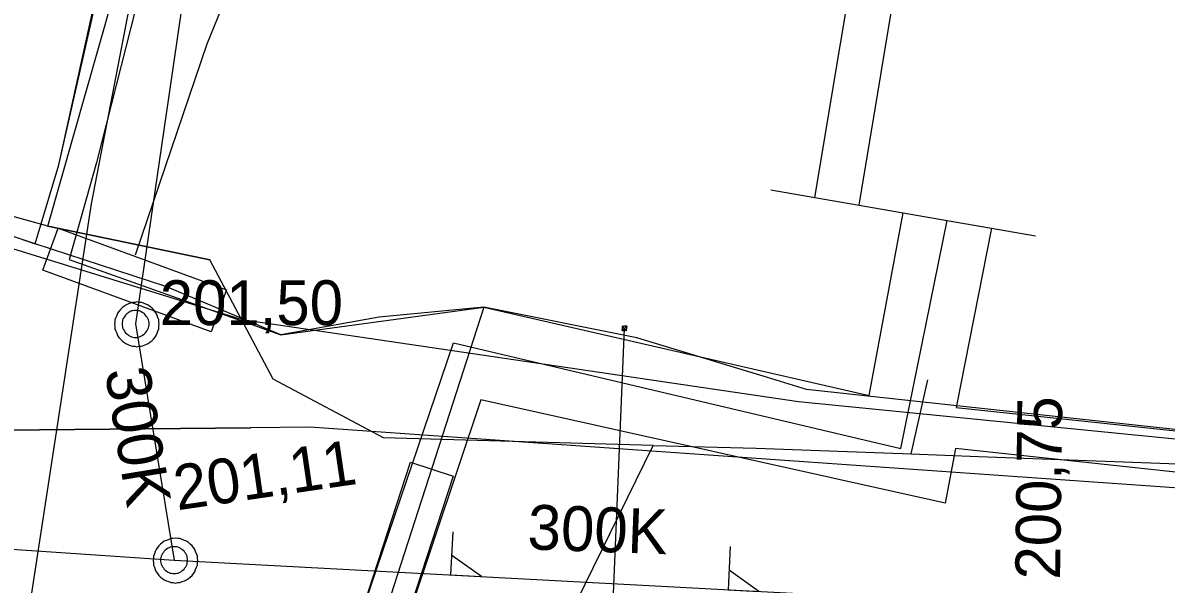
# Model space of a CAD drawing. Extents: x -746464 to -745690, y -1051581 to -1049993.
# Drawn here: x -746411.28 to -746385.76, y -1051025.44 to -1051012.91 of the extents above; entities that cross this region are included whole.
import ezdxf

# ---------------------------------------------------------------- set-up
doc = ezdxf.new("R2010")
doc.units = 0
for name, color, linetype in [('04_CETIN_NN', 7, 'Continuous'), ('04_CETIN_sdelovaci_podzem', 7, 'Continuous'), ('45_Eltodo_sdelovaci_kabel_ovladaci', 7, 'Continuous'), ('48_Prazs_plynarenska_STL', 7, 'Continuous'), ('51_PVaK_kanal_jednotna_overena poloha_rad', 7, 'Continuous'), ('51_PVaK_kanal_objekty', 7, 'Continuous'), ('51_PVaK_kanal_popisy', 7, 'Continuous'), ('51_PVaK_vodovod_chranicky_objekty', 7, 'Continuous'), ('51_PVaK_vodovod_overena poloha_pripojka', 7, 'Continuous'), ('55_PREdi_chranicky', 7, 'Continuous'), ('55_PREdi_NN', 7, 'Continuous'), ('55_PREdi_stavby_popisy', 7, 'Continuous')]:
    doc.layers.add(name, color=color, linetype=linetype)

msp = doc.modelspace()

# ---------------------------------------------------------------- linework, layer by layer
at = {"layer": '04_CETIN_NN'}
for points in [[(-746401.2, -1051030.47), (-746397.21, -1051022.34)], [(-746397.21, -1051022.34), (-746394.91, -1051022.4), (-746391.45, -1051022.53)], [(-746391.45, -1051022.53), (-746389.95, -1051022.59)], [(-746389.95, -1051022.59), (-746379.23, -1051022.98), (-746377.8, -1051022.62), (-746376.35, -1051023.07), (-746368.44, -1051023.67)]]:
    msp.add_lwpolyline(points, dxfattribs=at)
at = {"layer": '04_CETIN_sdelovaci_podzem'}
for points in [[(-746410.72, -1051017.45), (-746409.28, -1051012.4), (-746408.32, -1051005.09)], [(-746410.72, -1051017.45), (-746422.5, -1051014.18), (-746428.14, -1051011.55)], [(-746410.72, -1051017.45), (-746407.1, -1051018.2)], [(-746397.21, -1051022.34), (-746403.23, -1051022.17), (-746405.69, -1051020.86), (-746407.1, -1051018.2), (-746410.72, -1051017.45)], [(-746391.45, -1051022.53), (-746391.08, -1051020.88)], [(-746384.52, -1051023.36), (-746404.87, -1051021.93), (-746406.19, -1051021.95), (-746411.69, -1051022), (-746412.67, -1051021.99), (-746422.41, -1051022.74), (-746428.03, -1051023.83), (-746434.88, -1051025.34)], [(-746411.69, -1051022), (-746406.19, -1051021.95)], [(-746401.2, -1051030.47), (-746397.21, -1051022.34)], [(-746401.2, -1051030.47), (-746397.21, -1051022.34)], [(-746397.21, -1051022.34), (-746394.91, -1051022.4), (-746391.45, -1051022.53)], [(-746391.45, -1051022.53), (-746389.95, -1051022.59)], [(-746389.95, -1051022.59), (-746379.23, -1051022.98), (-746377.8, -1051022.62), (-746376.35, -1051023.07), (-746368.44, -1051023.67)]]:
    msp.add_lwpolyline(points, dxfattribs=at)
at = {"layer": '45_Eltodo_sdelovaci_kabel_ovladaci'}
msp.add_lwpolyline([(-746458.107, -1051040.596), (-746452.238, -1051038.914), (-746452.533, -1051024.817), (-746441.647, -1051021.908), (-746427.884, -1051017.81), (-746425.007, -1051017.632), (-746423.494, -1051014.247), (-746406.379, -1051019.532), (-746393.969, -1051021.364), (-746377.076, -1051023.037), (-746371.357, -1051023.39), (-746350.592, -1051020.748), (-746343.378, -1051018.106), (-746337.043, -1051014.584), (-746330.796, -1051018.194), (-746332.907, -1051022.157), (-746327.98, -1051025.591), (-746302.693, -1051026.653), (-746280.345, -1051027.533), (-746279.938, -1051027.788)], dxfattribs=at)
at = {"layer": '48_Prazs_plynarenska_STL'}
msp.add_lwpolyline([(-746411.209, -1051026.506), (-746409.74, -1051016.95), (-746407.07, -1051003.13), (-746406.45, -1050996.4), (-746406.4, -1050995.95)], dxfattribs=at)
at = {"layer": '51_PVaK_kanal_jednotna_overena poloha_rad'}
for p, q in [((-746408.76, -1051019.63), (-746407.9, -1051024.9)), ((-746407.9, -1051024.9), (-746388.25, -1051025.95))]:
    msp.add_line(p, q, dxfattribs=at)
for points in [[(-746405.53, -1050997.46), (-746406.021, -1051000.828), (-746406.251, -1051002.412), (-746408.76, -1051019.63)], [(-746423.55, -1051023.85), (-746414.385, -1051024.465), (-746407.9, -1051024.9)]]:
    msp.add_lwpolyline(points, dxfattribs=at)
at = {"layer": '51_PVaK_kanal_objekty'}
for points in [[(-746408.23, -1051019.64), (-746408.24, -1051019.59), (-746408.24, -1051019.54), (-746408.26, -1051019.49), (-746408.28, -1051019.44), (-746408.3, -1051019.39), (-746408.33, -1051019.35), (-746408.36, -1051019.31), (-746408.4, -1051019.27), (-746408.44, -1051019.24), (-746408.48, -1051019.21), (-746408.53, -1051019.19), (-746408.58, -1051019.17), (-746408.63, -1051019.15), (-746408.68, -1051019.15), (-746408.73, -1051019.14), (-746408.78, -1051019.15), (-746408.83, -1051019.15), (-746408.88, -1051019.17), (-746408.93, -1051019.19), (-746408.98, -1051019.21), (-746409.02, -1051019.24), (-746409.06, -1051019.27), (-746409.1, -1051019.31), (-746409.13, -1051019.35), (-746409.16, -1051019.39), (-746409.18, -1051019.44), (-746409.2, -1051019.49), (-746409.22, -1051019.54), (-746409.22, -1051019.59), (-746409.23, -1051019.64), (-746409.22, -1051019.69), (-746409.22, -1051019.74), (-746409.2, -1051019.79), (-746409.18, -1051019.84), (-746409.16, -1051019.89), (-746409.13, -1051019.93), (-746409.1, -1051019.97), (-746409.06, -1051020.01), (-746409.02, -1051020.04), (-746408.98, -1051020.07), (-746408.93, -1051020.09), (-746408.88, -1051020.11), (-746408.83, -1051020.13), (-746408.78, -1051020.13), (-746408.73, -1051020.14), (-746408.68, -1051020.13), (-746408.63, -1051020.13), (-746408.58, -1051020.11), (-746408.53, -1051020.09), (-746408.48, -1051020.07), (-746408.44, -1051020.04), (-746408.4, -1051020.01), (-746408.36, -1051019.97), (-746408.33, -1051019.93), (-746408.3, -1051019.89), (-746408.28, -1051019.84), (-746408.26, -1051019.79), (-746408.24, -1051019.74), (-746408.24, -1051019.69), (-746408.23, -1051019.64)], [(-746408.46, -1051019.63), (-746408.46, -1051019.6), (-746408.466, -1051019.57), (-746408.472, -1051019.54), (-746408.484, -1051019.51), (-746408.502, -1051019.48), (-746408.52, -1051019.456), (-746408.538, -1051019.432), (-746408.562, -1051019.408), (-746408.586, -1051019.39), (-746408.61, -1051019.372), (-746408.64, -1051019.354), (-746408.67, -1051019.342), (-746408.7, -1051019.336), (-746408.73, -1051019.33), (-746408.76, -1051019.33), (-746408.79, -1051019.33), (-746408.82, -1051019.336), (-746408.85, -1051019.342), (-746408.88, -1051019.354), (-746408.91, -1051019.372), (-746408.934, -1051019.39), (-746408.958, -1051019.408), (-746408.982, -1051019.432), (-746409, -1051019.456), (-746409.018, -1051019.48), (-746409.036, -1051019.51), (-746409.048, -1051019.54), (-746409.054, -1051019.57), (-746409.06, -1051019.6), (-746409.06, -1051019.63), (-746409.06, -1051019.66), (-746409.054, -1051019.69), (-746409.048, -1051019.72), (-746409.036, -1051019.75), (-746409.018, -1051019.78), (-746409, -1051019.804), (-746408.982, -1051019.828), (-746408.958, -1051019.852), (-746408.934, -1051019.87), (-746408.91, -1051019.888), (-746408.88, -1051019.906), (-746408.85, -1051019.918), (-746408.82, -1051019.924), (-746408.79, -1051019.93), (-746408.76, -1051019.93), (-746408.73, -1051019.93), (-746408.7, -1051019.924), (-746408.67, -1051019.918), (-746408.64, -1051019.906), (-746408.61, -1051019.888), (-746408.586, -1051019.87), (-746408.562, -1051019.852), (-746408.538, -1051019.828), (-746408.52, -1051019.804), (-746408.502, -1051019.78), (-746408.484, -1051019.75), (-746408.472, -1051019.72), (-746408.466, -1051019.69), (-746408.46, -1051019.66), (-746408.46, -1051019.63)], [(-746401.678, -1051024.266), (-746401.729, -1051025.23), (-746401.042, -1051025.266), (-746401.706, -1051024.795)], [(-746407.37, -1051024.91), (-746407.38, -1051024.86), (-746407.38, -1051024.81), (-746407.4, -1051024.76), (-746407.42, -1051024.71), (-746407.44, -1051024.66), (-746407.47, -1051024.62), (-746407.5, -1051024.58), (-746407.54, -1051024.54), (-746407.58, -1051024.51), (-746407.62, -1051024.48), (-746407.67, -1051024.46), (-746407.72, -1051024.44), (-746407.77, -1051024.42), (-746407.82, -1051024.42), (-746407.87, -1051024.41), (-746407.92, -1051024.42), (-746407.97, -1051024.42), (-746408.02, -1051024.44), (-746408.07, -1051024.46), (-746408.12, -1051024.48), (-746408.16, -1051024.51), (-746408.2, -1051024.54), (-746408.24, -1051024.58), (-746408.27, -1051024.62), (-746408.3, -1051024.66), (-746408.32, -1051024.71), (-746408.34, -1051024.76), (-746408.36, -1051024.81), (-746408.36, -1051024.86), (-746408.37, -1051024.91), (-746408.36, -1051024.96), (-746408.36, -1051025.01), (-746408.34, -1051025.06), (-746408.32, -1051025.11), (-746408.3, -1051025.16), (-746408.27, -1051025.2), (-746408.24, -1051025.24), (-746408.2, -1051025.28), (-746408.16, -1051025.31), (-746408.12, -1051025.34), (-746408.07, -1051025.36), (-746408.02, -1051025.38), (-746407.97, -1051025.4), (-746407.92, -1051025.4), (-746407.87, -1051025.41), (-746407.82, -1051025.4), (-746407.77, -1051025.4), (-746407.72, -1051025.38), (-746407.67, -1051025.36), (-746407.62, -1051025.34), (-746407.58, -1051025.31), (-746407.54, -1051025.28), (-746407.5, -1051025.24), (-746407.47, -1051025.2), (-746407.44, -1051025.16), (-746407.42, -1051025.11), (-746407.4, -1051025.06), (-746407.38, -1051025.01), (-746407.38, -1051024.96), (-746407.37, -1051024.91)], [(-746407.6, -1051024.9), (-746407.6, -1051024.87), (-746407.606, -1051024.84), (-746407.612, -1051024.81), (-746407.624, -1051024.78), (-746407.642, -1051024.75), (-746407.66, -1051024.726), (-746407.678, -1051024.702), (-746407.702, -1051024.678), (-746407.726, -1051024.66), (-746407.75, -1051024.642), (-746407.78, -1051024.624), (-746407.81, -1051024.612), (-746407.84, -1051024.606), (-746407.87, -1051024.6), (-746407.9, -1051024.6), (-746407.93, -1051024.6), (-746407.96, -1051024.606), (-746407.99, -1051024.612), (-746408.02, -1051024.624), (-746408.05, -1051024.642), (-746408.074, -1051024.66), (-746408.098, -1051024.678), (-746408.122, -1051024.702), (-746408.14, -1051024.726), (-746408.158, -1051024.75), (-746408.176, -1051024.78), (-746408.188, -1051024.81), (-746408.194, -1051024.84), (-746408.2, -1051024.87), (-746408.2, -1051024.9), (-746408.2, -1051024.93), (-746408.194, -1051024.96), (-746408.188, -1051024.99), (-746408.176, -1051025.02), (-746408.158, -1051025.05), (-746408.14, -1051025.074), (-746408.122, -1051025.098), (-746408.098, -1051025.122), (-746408.074, -1051025.14), (-746408.05, -1051025.158), (-746408.02, -1051025.176), (-746407.99, -1051025.188), (-746407.96, -1051025.194), (-746407.93, -1051025.2), (-746407.9, -1051025.2), (-746407.87, -1051025.2), (-746407.84, -1051025.194), (-746407.81, -1051025.188), (-746407.78, -1051025.176), (-746407.75, -1051025.158), (-746407.726, -1051025.14), (-746407.702, -1051025.122), (-746407.678, -1051025.098), (-746407.66, -1051025.074), (-746407.642, -1051025.05), (-746407.624, -1051025.02), (-746407.612, -1051024.99), (-746407.606, -1051024.96), (-746407.6, -1051024.93), (-746407.6, -1051024.9)], [(-746395.488, -1051024.597), (-746395.539, -1051025.56), (-746394.852, -1051025.597), (-746395.516, -1051025.126)]]:
    msp.add_lwpolyline(points, dxfattribs=at)
at = {"layer": '51_PVaK_vodovod_chranicky_objekty'}
for p, q in [((-746397.903, -1051019.777), (-746397.799, -1051019.681)), ((-746397.903, -1051019.777), (-746397.902, -1051019.757)), ((-746397.899, -1051019.677), (-746397.9, -1051019.697)), ((-746397.803, -1051019.781), (-746397.899, -1051019.677)), ((-746397.899, -1051019.677), (-746397.879, -1051019.678)), ((-746397.799, -1051019.681), (-746397.819, -1051019.68)), ((-746397.799, -1051019.681), (-746397.8, -1051019.701)), ((-746397.903, -1051019.777), (-746397.883, -1051019.778)), ((-746397.803, -1051019.781), (-746397.823, -1051019.78)), ((-746397.803, -1051019.781), (-746397.802, -1051019.761))]:
    msp.add_line(p, q, dxfattribs=at)
msp.add_lwpolyline([(-746397.849, -1051019.679), (-746397.854, -1051019.679), (-746397.859, -1051019.68), (-746397.864, -1051019.68), (-746397.869, -1051019.682), (-746397.874, -1051019.685), (-746397.878, -1051019.688), (-746397.882, -1051019.691), (-746397.887, -1051019.694), (-746397.89, -1051019.698), (-746397.893, -1051019.702), (-746397.896, -1051019.707), (-746397.898, -1051019.712), (-746397.899, -1051019.717), (-746397.901, -1051019.722), (-746397.901, -1051019.727), (-746397.901, -1051019.732), (-746397.9, -1051019.737), (-746397.9, -1051019.742), (-746397.898, -1051019.747), (-746397.895, -1051019.752), (-746397.892, -1051019.756), (-746397.889, -1051019.76), (-746397.885, -1051019.765), (-746397.882, -1051019.768), (-746397.878, -1051019.771), (-746397.873, -1051019.774), (-746397.868, -1051019.776), (-746397.863, -1051019.777), (-746397.858, -1051019.779), (-746397.853, -1051019.779), (-746397.848, -1051019.779), (-746397.843, -1051019.778), (-746397.838, -1051019.778), (-746397.833, -1051019.776), (-746397.828, -1051019.773), (-746397.824, -1051019.77), (-746397.82, -1051019.767), (-746397.815, -1051019.763), (-746397.812, -1051019.76), (-746397.809, -1051019.756), (-746397.806, -1051019.751), (-746397.804, -1051019.746), (-746397.802, -1051019.741), (-746397.801, -1051019.736), (-746397.801, -1051019.731), (-746397.801, -1051019.726), (-746397.802, -1051019.721), (-746397.802, -1051019.716), (-746397.804, -1051019.711), (-746397.807, -1051019.706), (-746397.81, -1051019.702), (-746397.813, -1051019.698), (-746397.816, -1051019.693), (-746397.82, -1051019.69), (-746397.824, -1051019.687), (-746397.829, -1051019.684), (-746397.834, -1051019.682), (-746397.839, -1051019.68), (-746397.844, -1051019.679), (-746397.849, -1051019.679)], dxfattribs=at)
at = {"layer": '51_PVaK_vodovod_overena poloha_pripojka'}
msp.add_line((-746398.15, -1051026.91), (-746397.85, -1051019.73), dxfattribs=at)
at = {"layer": '55_PREdi_chranicky'}
for points in [[(-746410.831, -1051018.432), (-746410.487, -1051017.494), (-746406.731, -1051018.869), (-746407.075, -1051019.807), (-746410.831, -1051018.432)], [(-746402.622, -1051022.714), (-746401.672, -1051023.025), (-746404.154, -1051030.63), (-746405.104, -1051030.319), (-746402.622, -1051022.714)]]:
    msp.add_lwpolyline(points, close=True, dxfattribs=at)
at = {"layer": '55_PREdi_NN'}
for points in [[(-746410.997, -1051017.845), (-746410.472, -1051016.082), (-746409.284, -1051010.839), (-746407.756, -1050996.625), (-746407.751, -1050990.419), (-746408.14, -1050985.416), (-746404.228, -1050978.997)], [(-746384.218, -1050991.777), (-746386.486, -1050988.899), (-746399.412, -1050984.014), (-746404.239, -1050979.835), (-746407.489, -1050985.767), (-746406.782, -1050996.737), (-746408.102, -1051009.995), (-746409.631, -1051016.029), (-746410.244, -1051018.195), (-746405.515, -1051019.874), (-746400.986, -1051019.255), (-746392.392, -1051021.23), (-746391.631, -1051017.155)], [(-746428.573, -1051010.988), (-746422.853, -1051013.746), (-746410.997, -1051017.845), (-746410.472, -1051016.082), (-746409.087, -1051009.798), (-746407.756, -1050996.625), (-746408.308, -1050986.107), (-746409.348, -1050986.162)], [(-746410.997, -1051017.845), (-746419.383, -1051015.06), (-746422.853, -1051013.746), (-746428.45, -1051011.047), (-746434.279, -1051008.237), (-746438.969, -1051004.698), (-746442.457, -1051001.544), (-746444.842, -1050999.388), (-746447.6, -1050996.762), (-746449.257, -1050995.632)], [(-746393.601, -1051016.813), (-746392.456, -1051009.946)], [(-746392.616, -1051016.984), (-746391.629, -1051011.069)], [(-746328.24, -1051013.684), (-746340.853, -1051017.038), (-746342.979, -1051017.603), (-746351.074, -1051020.516), (-746363.112, -1051022.249), (-746367.995, -1051022.985), (-746373.78, -1051023.267), (-746393.79, -1051021.091), (-746394.655, -1051020.827)], [(-746394.587, -1051016.642), (-746393.601, -1051016.813), (-746392.616, -1051016.984), (-746391.631, -1051017.155), (-746390.646, -1051017.325), (-746389.66, -1051017.496), (-746388.676, -1051017.667)], [(-746389.66, -1051017.496), (-746390.447, -1051021.495), (-746373.78, -1051023.267), (-746367.995, -1051022.985), (-746351.907, -1051020.543), (-746341.029, -1051016.873)], [(-746397.336, -1051057.726), (-746397.144, -1051055.927), (-746395.628, -1051036.016), (-746405.484, -1051031.281), (-746401.669, -1051020.053), (-746391.686, -1051022.407), (-746390.646, -1051017.325)], [(-746400.986, -1051019.255), (-746403.324, -1051019.479), (-746405.515, -1051019.874), (-746408.085, -1051018.797), (-746410.997, -1051017.845)], [(-746340.582, -1051017.778), (-746351.673, -1051021.52), (-746367.763, -1051024.007), (-746373.65, -1051024.219), (-746390.461, -1051022.407), (-746390.697, -1051023.631), (-746401.057, -1051021.324), (-746404.212, -1051030.74), (-746394.58, -1051035.412), (-746396.15, -1051056.033), (-746396.33, -1051057.725)], [(-746400.986, -1051019.255), (-746405.306, -1051032.615)], [(-746394.655, -1051020.827), (-746397.574, -1051019.938), (-746400.986, -1051019.255)]]:
    msp.add_lwpolyline(points, dxfattribs=at)
at = {"layer": '55_PREdi_stavby_popisy'}
msp.add_lwpolyline([(-746408.76, -1051018.09), (-746407.164, -1051013.383), (-746404.24, -1051006.2)], dxfattribs=at)

# ---------------------------------------------------------------- texts
at = {"layer": '51_PVaK_kanal_popisy'}
msp.add_text('201,50', height=1, dxfattribs=at).set_placement((-746408.221, -1051019.657))
for s, rotation, p in [('300K', 279.2676, (-746409.448, -1051020.676)), ('200,75', 89.3058, (-746388.131, -1051025.34)), ('201,11', 8.3528, (-746407.83, -1051023.79)), ('300K', 357.9408, (-746400.025, -1051024.657))]:
    msp.add_text(s, height=1, rotation=rotation, dxfattribs=at).set_placement(p)

doc.saveas('drawing.dxf')
